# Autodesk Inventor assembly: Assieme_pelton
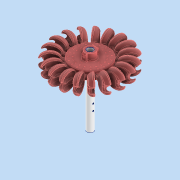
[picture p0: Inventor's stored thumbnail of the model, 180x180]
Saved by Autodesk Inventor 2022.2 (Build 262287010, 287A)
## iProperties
Created: 2025-03
Part Number: Assieme_pelton
Document SubType Name: Assembly
Designer: 18907419
Author: 18907419
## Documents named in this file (5)
- C:\Users\18907419\Desktop\banco turbine\Assieme_pelton.iam
- C:\Users\18907419\Desktop\banco turbine\disco pelton.ipt
- C:\Users\18907419\Desktop\banco turbine\albero-20mm.ipt
- C:\Users\18907419\Desktop\banco turbine\pala_pelton.ipt
- C:\Users\18907419\Desktop\banco turbine\disco pelton_MIR.ipt
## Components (22 placed, 4 different names)
1. disco pelton:1
2. albero-20mm:1
3. pala_pelton:1
4. pala_pelton:2
5. pala_pelton:3
6. pala_pelton:4
7. pala_pelton:5
8. pala_pelton:6
9. pala_pelton:7
10. pala_pelton:8
11. pala_pelton:9
12. pala_pelton:10
13. pala_pelton:11
14. pala_pelton:12
15. pala_pelton:13
16. pala_pelton:14
17. pala_pelton:15
18. pala_pelton:16
19. pala_pelton:17
20. pala_pelton:18
21. pala_pelton:19
22. disco pelton_MIR:1
